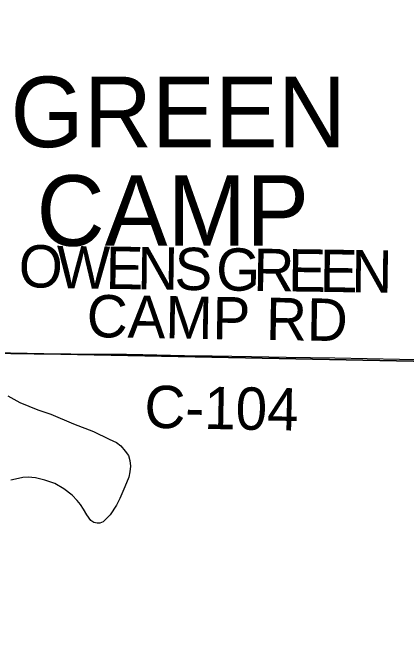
# Model space of a CAD drawing. Extents: x 1584893 to 1934202, y 663575 to 1091909.
# Drawn here: x 1772828 to 1775619, y 919483 to 923966 of the extents above; entities that cross this region are included whole.
import ezdxf

# ---------------------------------------------------------------- set-up
doc = ezdxf.new("R2010")
doc.units = 0
for name, color, linetype in [('GM_X_Corporation', 7, 'Continuous'), ('GM_X_Corporation_Text', 7, 'Continuous'), ('GM_X_County_Road', 7, 'Continuous'), ('GM_X_County_Road_Text', 7, 'Continuous'), ('GM_X_Section', 7, 'Continuous')]:
    doc.layers.add(name, color=color, linetype=linetype)

msp = doc.modelspace()

# ---------------------------------------------------------------- linework, layer by layer
at = {"layer": 'GM_X_Corporation'}
msp.add_lwpolyline([(1772794.4, 921251.9), (1772878.7, 921203), (1773005.5, 921151.1), (1773098.1, 921119.9), (1773258.2, 921052.4), (1773400.6, 920997.3), (1773512, 920944.5), (1773562.8, 920920.4), (1773595.1, 920895.5), (1773626.3, 920859.1), (1773648.1, 920827.9), (1773659.5, 920793.6), (1773662.7, 920753.1), (1773658.5, 920712.5), (1773650.2, 920674.1), (1773622.2, 920605.4), (1773586.8, 920522.3), (1773565, 920476.5), (1773518.3, 920407.9), (1773487.1, 920373.6), (1773468.4, 920358), (1773446.5, 920347.6), (1773425.7, 920347.6), (1773403.9, 920353.8), (1773381, 920366.3), (1773353, 920406.8), (1773329, 920447.3), (1773308.2, 920481.6), (1773284.3, 920508.7), (1773249, 920546.1), (1773190.7, 920591.8), (1773126.3, 920630.3), (1773056.6, 920654.1), (1772989, 920669.7), (1772938.1, 920673.9), (1772899.6, 920671.8), (1772869.5, 920665.5), (1772814.4, 920654.1)], dxfattribs=at)
at = {"layer": 'GM_X_County_Road'}
msp.add_lwpolyline([(1772711.3, 921554), (1772815.9, 921551.8), (1772864.9, 921550.9), (1772979.2, 921549.4), (1773126.6, 921548.3), (1773175.7, 921547.9), (1773241.2, 921547.6), (1773405.2, 921546.1), (1773634.6, 921545.2), (1773749.5, 921543.8), (1774044.9, 921536.6), (1774241.1, 921534), (1774519.9, 921528.8), (1774766, 921525.4), (1775110.6, 921520), (1775569.8, 921511.2), (1775881.2, 921503.9), (1775994.1, 921502), (1776191.3, 921497.2), (1776256.9, 921495.7), (1776437.2, 921491.4), (1776699.6, 921484.8), (1776725.4, 921484.1)], dxfattribs=at)
at = {"layer": 'GM_X_Section'}
msp.add_lwpolyline([(1771515.8, 926881.2), (1776827.6, 926748.9), (1776739.5, 921474.8), (1771379.6, 921581.5)], close=True, dxfattribs=at)
msp.add_lwpolyline([(1772311.8, 919482.1), (1772195.3, 919939.1), (1772161.4, 920031.3), (1772142.3, 920083.5), (1771947.5, 920499), (1771780.8, 920936.3), (1771716, 921108.9), (1771623.8, 921335.6), (1771548.8, 921466.2), (1771479.2, 921524.7), (1771379.6, 921581.5), (1776739.5, 921474.8), (1776623.4, 916198.9)], dxfattribs=at)

# ---------------------------------------------------------------- texts
at = {"layer": 'GM_X_Corporation_Text'}
for s, p in [('GREEN', (1772812.5, 923012.9)), ('CAMP', (1772997.3, 922314.1))]:
    msp.add_text(s, height=500, rotation=0, dxfattribs=at).set_placement(p)
at = {"layer": 'GM_X_County_Road_Text'}
for s, rotation, p in [('O', 357.7117, (1772865.5, 922024.7)), ('W', 359.2071, (1773137.8, 922014)), ('E', 359.1943, (1773485.4, 922009.2)), ('N', 359.1948, (1773709.8, 922006)), ('S', 359.1922, (1773973.7, 922002.3)), ('G', 359.1948, (1774268.5, 921998.1)), ('R', 359.1921, (1774532.5, 921994.4)), ('E', 359.1946, (1774778.9, 921991)), ('E', 359.1943, (1775003.3, 921987.8)), ('N', 359.1913, (1775227.7, 921984.6)), ('CAMP RD', 359.0836, (1773351.3, 921667.2)), ('C-104', 358.903, (1773759.8, 921024.9)), ('PROSPECT UPPER SANDUSK RD S', 294.4192, (1770475, 920131.2))]:
    msp.add_text(s, height=300, rotation=rotation, dxfattribs=at).set_placement(p)

doc.saveas('drawing.dxf')
